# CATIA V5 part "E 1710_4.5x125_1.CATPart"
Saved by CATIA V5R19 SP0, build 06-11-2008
Part number: E 1710_4.5x125_1
Definition: E 1710_4.5x125_1
Nomenclature: E 1710_4.5x125_1
Source: Unknown
Description: PART-E 1710_4.5x125_1-DESC
Bounding box of the stored display mesh (mm): x -4 to 4, y -3.991 to 3.991, z 0 to 109.067
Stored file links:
  C:\Users\jsmid\Desktop\DP_Smidak_Forma LEGO\E 1710_4.5x125_1.CATPart
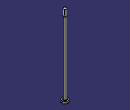
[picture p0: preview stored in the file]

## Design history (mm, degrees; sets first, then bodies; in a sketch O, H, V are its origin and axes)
Body1 "E 1710_4.5x125" (main body)
  Solid1: solid without history
  Sketch1 on face of Solid1, origin (0, 0, 125), H (1, 0, 0), V (0, 1, 0)
    circle A1 centre (0, 0) radius 2.9382
  Pocket1: profile Sketch1, direction (0, 0, -1), length 15.933
  Sketch2 on zx-plane, origin (0, 0, 0), H (-1, 0, 0), V (0, 0, 1)
    axis line L1 (0, 0) -> (0, 230.083)
    point P1 (0, 230.083)
    line L2 (4.4624, 109.067) -> (2.1, 109.067)
    point P2 (2.1, 109.067)
    line L3 (2.1, 109.067) -> (2.25, 100.423)
    point P3 (2.25, 100.423)
    line L4 (2.25, 100.423) -> (4.4624, 100.423)
    reference projected line E1 (2.25, 109.067) -> (-2.25, 109.067) from edge [face of Solid1 | end face of Pocket1]
    line L5 (4.4624, 100.423) -> (4.4624, 109.067)
    length L5 = 8.644
    distance P2 L1 = 2.1
    distance P3 L1 = 2.25
    vertical: L1 V, L5 V
    horizontal: L2 H, L4 H
    coincidence: L3 P1, L2 E1
  Groove1: profile Sketch2, axis Sketch2.L1, angle 360
  DatumSurface1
